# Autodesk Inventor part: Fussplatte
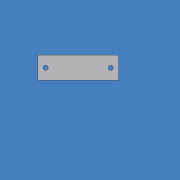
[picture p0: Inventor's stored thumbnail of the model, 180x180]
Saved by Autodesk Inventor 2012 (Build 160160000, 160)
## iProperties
Company: CAD-Verlag
Shininess: 64.0
Length Units: 11269
Angle Units: 11279
Time Units: 11290
Mass Units: 11283
Length Display Precision: 3
Angle Display Precision: 2
Compacted: True
Part Number: Fussplatte
Document SubType Name: Modeling
Created: 2004-09
Material: Standard
Designer: Greiling
Manufacturer: Standard
Standards Organization: Custom
Density: 1 g/cm^3
Density: 0.0
Volumn: 0.0
Area: 0.0
PropertySet Name: Model Information
Control State: 0
Master: False
Checked Out: False
Author: Jürgen Kronas
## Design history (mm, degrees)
sketch "Skizze1"
  geometry: L1 (0, 64)-(0, -48) reference; L2 (-156, 0)-(208, 0) reference; L3 (-156, 0)-(208, 0) reference; L4 (0, -48)-(0, 64) reference; L5 (-130, 40)-(130, 40); L6 (130, 40)-(130, -40); L7 (130, -40)-(-130, -40); L8 (-130, -40)-(-130, 40); C1 r 9 at (-105, 0); C2 r 9 at (105, 0); 1 further point
  constraints: 8 end point, 2 centre point, 2 parallel, 1 horizontal, 1 perpendicular, 1 point on line, 1 symmetric about line, 3 other
  dimensions: "d0" = 80 distance of L7.end L5.start; "d1" = 260 distance of L5.start L5.end; "d2" = 18 diameter of C1; "d3" = 210 distance of C2.centre C1.centre
extrude "Extrusion1" new body sketch "Skizze1" distance "d4" = 10; taper "d5" = 0 deg
node "Volumenkörper1"
node "Volumenkörpern"
node "Oberflächenkörpern"
